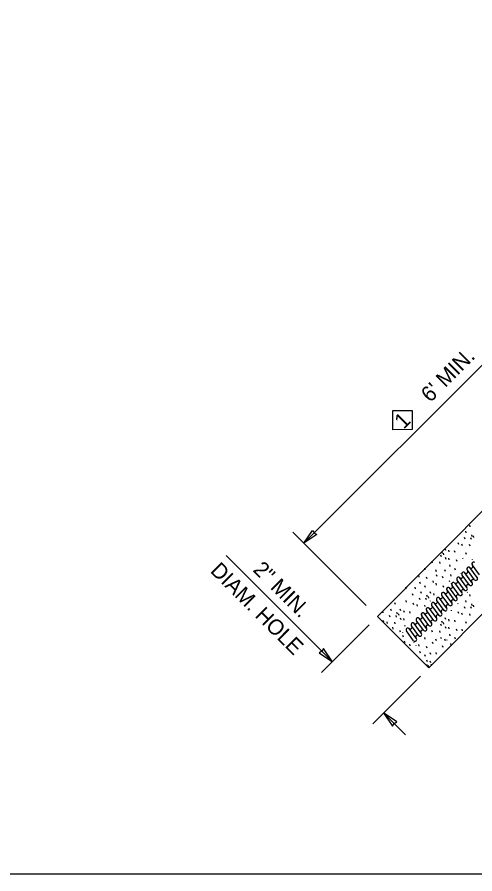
# Model space of a CAD drawing. Extents: x 99861 to 103151, y 100000 to 102076.
# Drawn here: x 101342 to 101816, y 100000 to 100887 of the extents above; entities that cross this region are included whole.
import ezdxf

# ---------------------------------------------------------------- set-up
doc = ezdxf.new("R2010")
doc.units = 0
for name, color, linetype in [('Level 1', 7, 'Continuous'), ('Level 15', 7, 'Continuous'), ('Level 2', 7, 'Continuous'), ('Level 20', 7, 'Continuous'), ('Level 8', 7, 'Continuous')]:
    doc.layers.add(name, color=color, linetype=linetype)

# ---------------------------------------------------------------- blocks, each defined once
blk = doc.blocks.new('T')
at = {"layer": 'Level 15'}
blk.add_lwpolyline([(0, 0), (-22.829, 2.985), (-21.773, 0), (-22.83, -2.985)], close=True, dxfattribs=at)

msp = doc.modelspace()

# ---------------------------------------------------------------- linework, layer by layer
at = {"layer": 'Level 1'}
for p, q in [((101817.93, 100306.87), (101810.54, 100316.96)), ((101820.56, 100309.5), (101813.15, 100319.59)), ((101807.45, 100296.39), (101800.04, 100306.47)), ((101801.11, 100310.83), (101801.04, 100310.52)), ((101810.06, 100299), (101802.67, 100309.09)), ((101812.69, 100301.63), (101805.3, 100311.72)), ((101815.31, 100304.24), (101807.91, 100314.33)), ((101791.29, 100300.91), (101791.13, 100300.7)), ((101799.57, 100288.52), (101792.18, 100298.6)), ((101802.2, 100291.13), (101794.8, 100301.22)), ((101804.82, 100293.76), (101797.43, 100303.84)), ((101789.09, 100278.02), (101781.69, 100288.11)), ((101791.7, 100280.64), (101784.31, 100290.73)), ((101786.93, 100293.36), (101794.33, 100283.27)), ((101796.95, 100285.89), (101789.55, 100295.98)), ((101807.88, 100291.36), (101808.14, 100291.67)), ((101781.22, 100270.16), (101773.82, 100280.25)), ((101783.84, 100272.78), (101776.44, 100282.86)), ((101786.46, 100275.4), (101779.07, 100285.49)), ((101765.73, 100275.45), (101765.66, 100275.14)), ((101773.35, 100262.29), (101765.96, 100272.38)), ((101775.98, 100264.91), (101768.57, 100274.99)), ((101778.59, 100267.53), (101771.2, 100277.62)), ((101762.86, 100251.8), (101755.46, 100261.88)), ((101765.48, 100254.42), (101758.09, 100264.51)), ((101768.11, 100257.04), (101760.71, 100267.13)), ((101770.72, 100259.66), (101763.33, 100269.75)), ((101744.75, 100254.47), (101744.68, 100254.16)), ((101755, 100243.93), (101747.59, 100254.01)), ((101757.61, 100246.55), (101750.22, 100256.64)), ((101760.24, 100249.18), (101752.84, 100259.27)), ((101740.99, 100249.77), (101740.93, 100249.45)), ((101752.37, 100241.31), (101744.98, 100251.4)), ((101752.44, 100239.62), (101752.38, 100239.3))]:
    msp.add_line(p, q, dxfattribs=at)
msp.add_lwpolyline([(99861, 100000), (103150, 100000), (103150, 102076), (99861, 102076)], close=True, dxfattribs=at)
for centre, start, end in [((101809.23, 100315.65), 44.99981, 225.00019), ((101811.85, 100318.27), 225.00019, 44.99981), ((101814.47, 100320.89), 44.99981, 225.00019), ((101798.74, 100305.16), 44.99981, 225.00019), ((101801.36, 100307.78), 225.00019, 44.99981), ((101803.98, 100310.4), 44.99981, 225.00019), ((101806.6, 100313.02), 225.00019, 44.99981), ((101816.62, 100305.56), 225.00019, 44.99981), ((101790.87, 100297.29), 225.00019, 44.99981), ((101793.49, 100299.91), 44.99981, 225.00019), ((101793.49, 100299.91), 162.38711, 225.00019), ((101796.11, 100302.53), 225.00019, 44.99981), ((101808.75, 100297.69), 44.99981, 225.00019), ((101811.38, 100300.31), 225.00019, 44.99981), ((101814, 100302.94), 44.99981, 225.00019), ((101780.38, 100286.8), 225.00019, 44.99981), ((101783, 100289.42), 44.99981, 225.00019), ((101785.62, 100292.04), 225.00019, 44.99981), ((101788.25, 100294.67), 44.99981, 225.00019), ((101798.26, 100287.2), 44.99981, 225.00019), ((101800.89, 100289.82), 225.00019, 44.99981), ((101800.89, 100289.82), 225.00019, 349.51811), ((101803.51, 100292.45), 44.99981, 225.00019), ((101806.13, 100295.07), 225.00019, 44.99981), ((101772.51, 100278.93), 44.99981, 225.00019), ((101775.13, 100281.55), 225.00019, 44.99981), ((101777.76, 100284.18), 44.99981, 225.00019), ((101790.4, 100279.33), 225.00019, 44.99981), ((101793.02, 100281.96), 44.99981, 225.00019), ((101795.64, 100284.58), 225.00019, 44.99981), ((101793.02, 100281.96), 44.99981, 45.01037), ((101762.02, 100268.44), 44.99981, 225.00019), ((101764.65, 100271.06), 225.00019, 44.99981), ((101767.27, 100273.69), 44.99981, 225.00019), ((101769.89, 100276.31), 225.00019, 44.99981), ((101779.91, 100268.84), 225.00019, 44.99981), ((101782.53, 100271.47), 44.99981, 225.00019), ((101785.15, 100274.09), 225.00019, 44.99981), ((101787.77, 100276.71), 44.99981, 225.00019), ((101754.16, 100260.57), 225.00019, 44.99981), ((101756.78, 100263.19), 44.99981, 225.00019), ((101759.4, 100265.82), 225.00019, 44.99981), ((101772.04, 100260.97), 44.99981, 225.00019), ((101774.66, 100263.6), 225.00019, 44.99981), ((101777.28, 100266.22), 44.99981, 225.00019), ((101746.29, 100252.7), 44.99981, 225.00019), ((101748.91, 100255.33), 225.00019, 44.99981), ((101751.53, 100257.95), 44.99981, 225.00019), ((101761.55, 100250.48), 44.99981, 225.00019), ((101764.17, 100253.11), 225.00019, 44.99981), ((101766.8, 100255.73), 44.99981, 225.00019), ((101769.42, 100258.35), 225.00019, 44.99981), ((101753.68, 100242.62), 225.00019, 44.99981), ((101756.31, 100245.24), 44.99981, 225.00019), ((101758.93, 100247.86), 225.00019, 44.99981)]:
    msp.add_arc(centre, 1.85, start, end, dxfattribs=at)
at = {"layer": 'Level 15'}
for p, q in [((101638.87, 100342.28), (101934.1, 100637.78)), ((101703.21, 100277.92), (101627.38, 100353.82))]:
    msp.add_line(p, q, dxfattribs=at)
for points in [[(101638.87, 100342.28), (101647.8, 100355.58), (101649.47, 100352.89), (101652.16, 100351.22)], [(101808.08, 100296.52), (101808.08, 100296.52), (101808.08, 100296.52), (101808.08, 100296.52)], [(101808.08, 100296.52), (101808.08, 100296.52), (101808.08, 100296.52), (101808.08, 100296.52)], [(101808.08, 100296.52), (101808.08, 100296.52), (101808.08, 100296.52), (101808.08, 100296.52)], [(101808.08, 100296.52), (101808.08, 100296.52), (101808.08, 100296.52), (101808.08, 100296.52)], [(101808.08, 100296.52), (101808.08, 100296.52), (101808.08, 100296.52), (101808.08, 100296.52)]]:
    msp.add_lwpolyline(points, close=True, dxfattribs=at)
at = {"layer": 'Level 2'}
for p, q in [((101836.78, 100388.98), (101714.91, 100266.28)), ((101810.98, 100359.19), (101810.41, 100360.94)), ((101806.82, 100352.92), (101806.24, 100354.67)), ((101813.03, 100349.35), (101812.46, 100351.1)), ((101798.97, 100341.04), (101798.4, 100342.79)), ((101802.9, 100339.61), (101802.32, 100341.35)), ((101805.56, 100346.39), (101804.99, 100348.13)), ((101812.19, 100346.13), (101811.61, 100347.88)), ((101814.71, 100348.05), (101814.14, 100349.79)), ((101889.84, 100335.95), (101767.98, 100213.25)), ((101782.04, 100331.46), (101781.47, 100333.2)), ((101785.54, 100334.83), (101784.96, 100336.58)), ((101789.23, 100333.33), (101788.66, 100335.08)), ((101795.36, 100332.55), (101794.79, 100334.3)), ((101806.88, 100330.69), (101806.31, 100332.44)), ((101810.88, 100339.19), (101810.31, 100340.93)), ((101771.9, 100321.71), (101771.33, 100323.46)), ((101781.19, 100328.24), (101780.62, 100329.98)), ((101783.72, 100330.15), (101783.14, 100331.9)), ((101785.93, 100325.56), (101785.36, 100327.3)), ((101789.2, 100325.13), (101788.63, 100326.87)), ((101797.27, 100323.21), (101796.7, 100324.95)), ((101803.62, 100326.12), (101803.4, 100326.8)), ((101813.36, 100325.54), (101813.32, 100325.65)), ((101764.37, 100314.66), (101763.8, 100316.4)), ((101775.89, 100312.79), (101775.32, 100314.54)), ((101779.88, 100321.29), (101779.31, 100323.04)), ((101785.34, 100312.84), (101784.77, 100314.58)), ((101790.29, 100318.01), (101789.71, 100319.76)), ((101795.49, 100314.44), (101794.92, 100316.19)), ((101758.21, 100307.23), (101757.64, 100308.98)), ((101766.28, 100305.31), (101765.71, 100307.06)), ((101768.14, 100313.56), (101768.13, 100313.61)), ((101776.57, 100307.78), (101775.99, 100309.53)), ((101782.9, 100306.01), (101782.33, 100307.76)), ((101791.33, 100308.17), (101790.76, 100309.91)), ((101744.89, 100294.9), (101744.32, 100296.65)), ((101754.35, 100294.94), (101753.78, 100296.69)), ((101759.29, 100300.12), (101758.72, 100301.86)), ((101764.5, 100296.55), (101763.93, 100298.29)), ((101773.02, 100301.43), (101772.45, 100303.18)), ((101776.12, 100299), (101775.54, 100300.74)), ((101783.48, 100296.29), (101782.91, 100298.03)), ((101789.89, 100302.19), (101789.5, 100303.38)), ((101751.9, 100288.12), (101751.33, 100289.86)), ((101760.33, 100290.27), (101759.76, 100292.02)), ((101766.55, 100286.71), (101765.98, 100288.45)), ((101770.05, 100290.08), (101769.48, 100291.82)), ((101773.74, 100288.58), (101773.17, 100290.33)), ((101811, 100287.59), (101810.43, 100289.33)), ((101733.5, 100278.65), (101732.93, 100280.4)), ((101745.12, 100281.1), (101744.55, 100282.85)), ((101752.49, 100278.39), (101751.92, 100280.14)), ((101759.07, 100283.74), (101758.5, 100285.49)), ((101765.7, 100283.49), (101765.13, 100285.23)), ((101768.23, 100285.4), (101767.65, 100287.15)), ((101769.94, 100282.34), (101769.87, 100282.55)), ((101798.41, 100279.15), (101798.19, 100279.81)), ((101806.83, 100281.31), (101806.26, 100283.06)), ((101813.05, 100277.74), (101812.48, 100279.49)), ((101720.91, 100270.22), (101720.34, 100271.97)), ((101729.34, 100272.38), (101728.77, 100274.12)), ((101735.55, 100268.81), (101734.98, 100270.56)), ((101739.05, 100272.18), (101738.48, 100273.93)), ((101742.74, 100270.69), (101742.17, 100272.43)), ((101748.88, 100269.9), (101748.31, 100271.65)), ((101756.41, 100276.96), (101755.84, 100278.71)), ((101764.32, 100276.76), (101763.82, 100278.29)), ((101791.62, 100272.14), (101791.35, 100272.97)), ((101798.99, 100269.43), (101798.42, 100271.18)), ((101805.57, 100274.78), (101805, 100276.53)), ((101812.2, 100274.52), (101811.63, 100276.27)), ((101814.73, 100276.44), (101814.16, 100278.19)), ((101767.98, 100213.25), (101714.91, 100266.28)), ((101767.98, 100213.25), (101718.73, 100262.47)), ((101721.49, 100260.5), (101720.92, 100262.24)), ((101728.08, 100265.85), (101727.51, 100267.59)), ((101734.71, 100265.59), (101734.13, 100267.34)), ((101737.23, 100267.51), (101736.66, 100269.25)), ((101739.45, 100262.91), (101738.87, 100264.66)), ((101742.72, 100262.48), (101742.15, 100264.23)), ((101782.06, 100259.85), (101781.48, 100261.6)), ((101785.55, 100263.22), (101784.98, 100264.97)), ((101789.24, 100261.73), (101788.67, 100263.47)), ((101795.38, 100260.94), (101794.81, 100262.69)), ((101802.91, 100268), (101802.34, 100269.75)), ((101810.89, 100267.58), (101810.32, 100269.32)), ((101725.42, 100259.07), (101724.84, 100260.81)), ((101731.34, 100253.44), (101730.77, 100255.19)), ((101733.4, 100258.64), (101732.83, 100260.39)), ((101743.56, 100256.1), (101743.23, 100257.11)), ((101781.21, 100256.63), (101780.64, 100258.38)), ((101783.73, 100258.54), (101783.16, 100260.29)), ((101785.95, 100253.95), (101785.37, 100255.69)), ((101789.22, 100253.52), (101788.65, 100255.26)), ((101797.29, 100251.6), (101796.72, 100253.35)), ((101802.94, 100251.68), (101802.39, 100253.37)), ((101806.9, 100259.08), (101806.33, 100260.83)), ((101738.55, 100251.12), (101738.29, 100251.94)), ((101738.86, 100250.19), (101738.58, 100251.05)), ((101741.87, 100245.04), (101741.3, 100246.79)), ((101764.38, 100243.05), (101763.81, 100244.79)), ((101771.92, 100250.1), (101771.34, 100251.85)), ((101779.9, 100249.68), (101779.33, 100251.43)), ((101781.09, 100243.33), (101780.6, 100244.83)), ((101790.3, 100246.4), (101789.73, 100248.15)), ((101795.51, 100242.83), (101794.94, 100244.58)), ((101743.58, 100238.99), (101743.01, 100240.74)), ((101748.9, 100235.87), (101748.33, 100237.61)), ((101754.95, 100236.05), (101754.82, 100236.44)), ((101758.22, 100235.62), (101757.65, 100237.37)), ((101766.3, 100233.71), (101765.72, 100235.45)), ((101772.39, 100238.23), (101771.82, 100239.98)), ((101775.9, 100241.19), (101775.33, 100242.93)), ((101782.92, 100234.4), (101782.34, 100236.15)), ((101785.36, 100241.23), (101784.79, 100242.98)), ((101786.87, 100241.69), (101786.68, 100242.28)), ((101791.34, 100236.56), (101790.77, 100238.31)), ((101759.31, 100228.51), (101758.73, 100230.26)), ((101764.51, 100224.94), (101763.94, 100226.69)), ((101770.17, 100226.94), (101769.6, 100228.68)), ((101776.13, 100227.39), (101775.56, 100229.14)), ((101766.57, 100219.54), (101765.99, 100221.29)), ((101766.57, 100215.1), (101765.99, 100216.84)), ((101770.06, 100218.47), (101769.49, 100220.22)), ((101768.24, 100213.79), (101767.67, 100215.54))]:
    msp.add_line(p, q, dxfattribs=at)
at = {"layer": 'Level 20'}
for p, q in [((101668.26, 100219.6), (101558.27, 100329.52)), ((101706.43, 100257.8), (101656.95, 100208.28)), ((101656.94, 100230.91), (101668.26, 100219.6)), ((101759.5, 100204.77), (101710.01, 100155.25)), ((101743.96, 100143.95), (101721.32, 100166.57))]:
    msp.add_line(p, q, dxfattribs=at)
msp.add_lwpolyline([(101730.86, 100479.54), (101750.72, 100479.65), (101750.83, 100459.79), (101730.97, 100459.68)], close=True, dxfattribs=at)
at = {"layer": 'Level 8'}
for p, q in [((101770.12, 100217), (101770.06, 100216.69)), ((101767.57, 100213.95), (101767, 100215.7))]:
    msp.add_line(p, q, dxfattribs=at)

# ---------------------------------------------------------------- block references
at = {"layer": 'Level 20', "xscale": 0.700832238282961}
for p, yscale, rotation in [((101668.26, 100219.6), 1.0720268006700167, -44.98115163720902), ((101721.32, 100166.57), 1.072026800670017, 135.01884836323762)]:
    msp.add_blockref('T', p, dxfattribs=dict(at, yscale=yscale, rotation=rotation))

# ---------------------------------------------------------------- texts
at = {"layer": 'Level 20'}
for s, rotation, p in [("6' MIN.", 45.02609, (101769.57, 100487.2)), ('1', 45.02609, (101742.05, 100459.54)), ('DIAM. HOLE ', 315.01885, (101541.04, 100312.8)), ('2" MIN.', 315.01885, (101585.28, 100313.84))]:
    msp.add_text(s, height=16, rotation=rotation, dxfattribs=at).set_placement(p)

doc.saveas('drawing.dxf')
